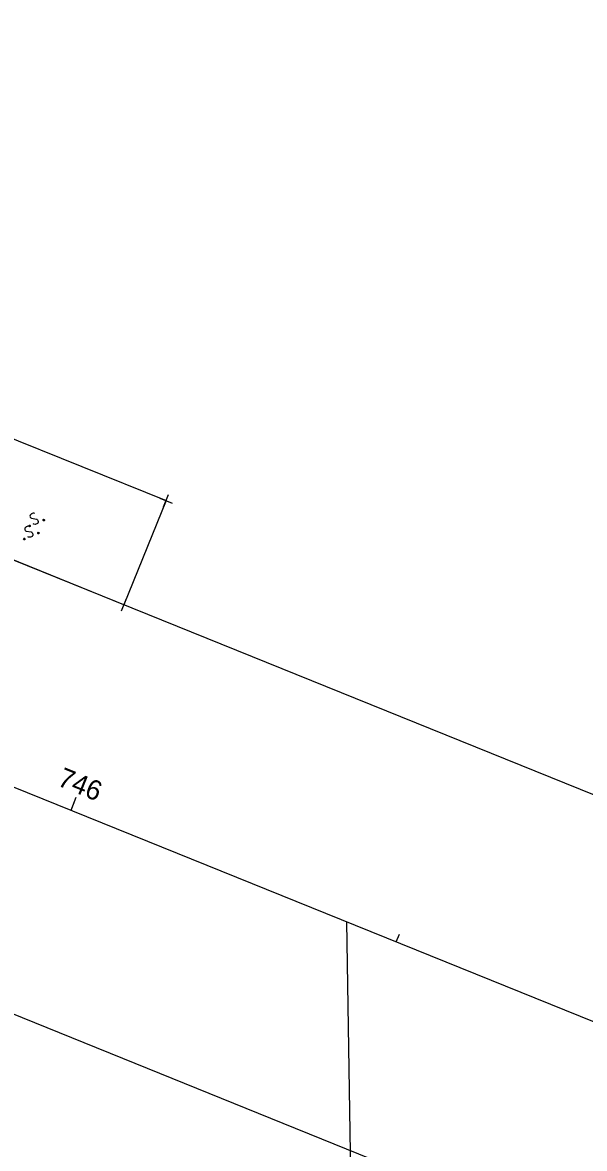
# Model space of a CAD drawing. Extents: x 2345526 to 2352057, y 624934 to 629976.
# Drawn here: x 2347352.4 to 2347432.5, y 627418.4 to 627578.9 of the extents above; entities that cross this region are included whole.
import ezdxf

# ---------------------------------------------------------------- set-up
doc = ezdxf.new("R2010")
doc.units = 0
for name, color, linetype in [('DT_X_TIN_Hull', 7, 'Continuous'), ('DT_X_Void', 7, 'Continuous'), ('RW_P_Esmt_SH', 7, 'Continuous'), ('RW_P_Esmt_TMP', 7, 'Continuous'), ('RW_X_CL', 7, 'Continuous'), ('RW_X_CL_100_Cardinal_Points', 7, 'Continuous'), ('RW_X_CL_500_Cardinal_Points', 7, 'Continuous'), ('RW_X_Esmt_SH', 7, 'Continuous')]:
    doc.layers.add(name, color=color, linetype=linetype)

msp = doc.modelspace()

# ---------------------------------------------------------------- linework, layer by layer
at = {"layer": 'DT_X_TIN_Hull'}
for p, q in [((2347214.38, 627574.89), (2347372.89, 627510.74)), ((2347372.89, 627510.74), (2347366.88, 627495.91)), ((2347372.01, 627511.09), (2347373.76, 627510.38)), ((2347372.53, 627509.86), (2347373.24, 627511.61)), ((2347366.88, 627495.91), (2347347.42, 627503.78)), ((2347366.01, 627496.26), (2347367.76, 627495.55)), ((2347366.53, 627495.03), (2347367.24, 627496.78))]:
    msp.add_line(p, q, dxfattribs=at)
at = {"layer": 'DT_X_Void'}
for points in [[(2347354.13, 627508.91), (2347354.1, 627508.93), (2347354.06, 627508.94), (2347353.96, 627508.93), (2347353.83, 627508.91), (2347353.75, 627508.88), (2347353.72, 627508.86), (2347353.61, 627508.77), (2347353.52, 627508.66), (2347353.49, 627508.53), (2347353.51, 627508.43), (2347353.54, 627508.36), (2347353.6, 627508.28), (2347353.72, 627508.23), (2347354.42, 627508.12), (2347354.49, 627508.09), (2347354.53, 627508.06), (2347354.58, 627508), (2347354.61, 627507.93), (2347354.63, 627507.85), (2347354.64, 627507.8), (2347354.64, 627507.73), (2347354.64, 627507.68), (2347354.64, 627507.64), (2347354.62, 627507.59), (2347354.6, 627507.55), (2347354.57, 627507.51), (2347354.55, 627507.49), (2347354.46, 627507.44), (2347354.32, 627507.38), (2347354.22, 627507.36), (2347354.05, 627507.39), (2347353.94, 627507.42)], [(2347353.38, 627507.06), (2347353.35, 627507.07), (2347353.31, 627507.08), (2347353.21, 627507.08), (2347353.08, 627507.06), (2347353, 627507.02), (2347352.97, 627507.01), (2347352.86, 627506.92), (2347352.77, 627506.8), (2347352.74, 627506.68), (2347352.76, 627506.58), (2347352.79, 627506.51), (2347352.85, 627506.42), (2347352.97, 627506.38), (2347353.67, 627506.27), (2347353.74, 627506.24), (2347353.78, 627506.2), (2347353.83, 627506.14), (2347353.86, 627506.07), (2347353.88, 627506), (2347353.89, 627505.95), (2347353.89, 627505.88), (2347353.89, 627505.83), (2347353.89, 627505.78), (2347353.87, 627505.73), (2347353.85, 627505.7), (2347353.82, 627505.66), (2347353.8, 627505.63), (2347353.71, 627505.58), (2347353.57, 627505.52), (2347353.47, 627505.51), (2347353.3, 627505.53), (2347353.19, 627505.57)], [(2347353.37, 627507.21), (2347353.42, 627507.23), (2347353.46, 627507.22), (2347353.51, 627507.19), (2347353.54, 627507.13), (2347353.53, 627507.07), (2347353.5, 627507.03), (2347353.45, 627507.01), (2347353.41, 627507.02), (2347353.36, 627507.06), (2347353.34, 627507.11), (2347353.35, 627507.17), (2347353.37, 627507.21)], [(2347355.38, 627508.06), (2347355.43, 627508.08), (2347355.47, 627508.07), (2347355.52, 627508.04), (2347355.55, 627507.98), (2347355.54, 627507.92), (2347355.51, 627507.88), (2347355.46, 627507.86), (2347355.42, 627507.87), (2347355.37, 627507.91), (2347355.35, 627507.96), (2347355.36, 627508.02), (2347355.38, 627508.06)], [(2347352.62, 627505.35), (2347352.67, 627505.38), (2347352.71, 627505.37), (2347352.76, 627505.33), (2347352.79, 627505.27), (2347352.78, 627505.22), (2347352.75, 627505.18), (2347352.7, 627505.16), (2347352.66, 627505.17), (2347352.61, 627505.2), (2347352.59, 627505.26), (2347352.6, 627505.32), (2347352.62, 627505.35)], [(2347354.63, 627506.21), (2347354.68, 627506.23), (2347354.72, 627506.22), (2347354.77, 627506.18), (2347354.8, 627506.13), (2347354.78, 627506.07), (2347354.76, 627506.03), (2347354.71, 627506.01), (2347354.67, 627506.02), (2347354.62, 627506.05), (2347354.6, 627506.11), (2347354.61, 627506.17), (2347354.63, 627506.21)]]:
    msp.add_lwpolyline(points, dxfattribs=at)
at = {"layer": 'RW_P_Esmt_SH'}
for p, q in [((2347214.38, 627574.89), (2347372.89, 627510.74)), ((2347372.89, 627510.74), (2347366.88, 627495.91))]:
    msp.add_line(p, q, dxfattribs=at)
at = {"layer": 'RW_P_Esmt_TMP'}
msp.add_line((2347398.61, 627450.7), (2347422.73, 625906.99), dxfattribs=at)
at = {"layer": 'RW_X_CL'}
msp.add_line((2345617.75, 628171.49), (2348868.68, 626855.7), dxfattribs=at)
at = {"layer": 'RW_X_CL_100_Cardinal_Points'}
for p, q in [((2347359.34, 627466.6), (2347360.09, 627468.45)), ((2347405.68, 627447.84), (2347406.13, 627448.95))]:
    msp.add_line(p, q, dxfattribs=at)
at = {"layer": 'RW_X_CL_500_Cardinal_Points'}
msp.add_line((2347359.34, 627466.6), (2347359.79, 627467.71), dxfattribs=at)
at = {"layer": 'RW_X_Esmt_SH'}
for p, q in [((2346860.77, 627700.75), (2347555.98, 627419.37)), ((2347255.39, 627476.31), (2347533.47, 627363.75))]:
    msp.add_line(p, q, dxfattribs=at)

# ---------------------------------------------------------------- texts
at = {"layer": 'RW_X_CL_100_Cardinal_Points'}
msp.add_text('746', height=2.8, rotation=337.9647, dxfattribs=at).set_placement((2347357.25, 627470.19))

doc.saveas('drawing.dxf')
